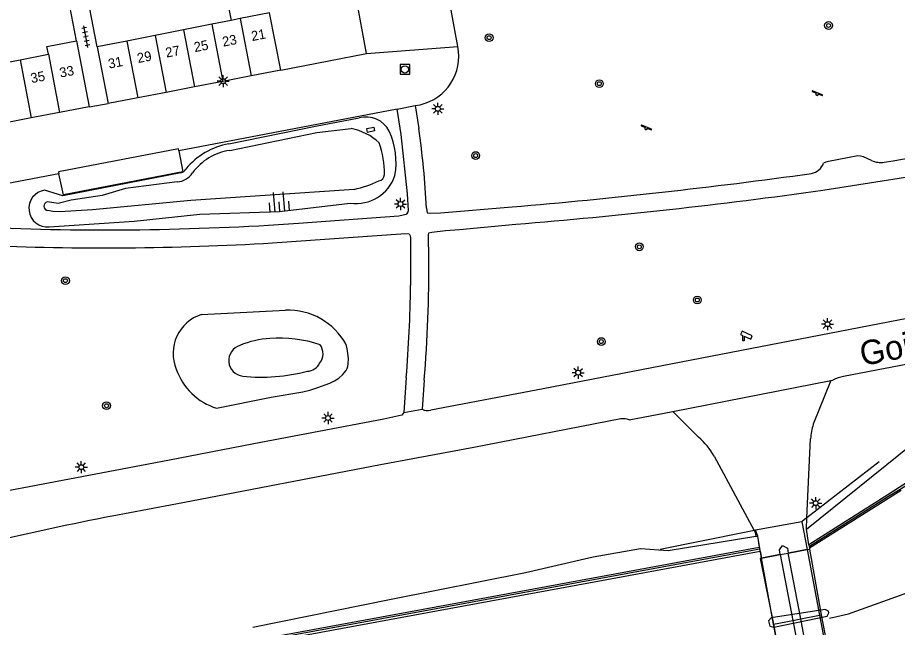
# Model space of a CAD drawing. Extents: x 132999 to 136000, y 398499 to 400501.
# Drawn here: x 133396.4 to 133486.8, y 398848.7 to 398911.3 of the extents above; entities that cross this region are included whole.
import ezdxf

# ---------------------------------------------------------------- set-up
doc = ezdxf.new("R2010")
doc.units = 0
for name, color, linetype in [('gg-afsc-erfafscheiding', 7, 'Continuous'), ('gg-afsc-hekwerk', 7, 'Continuous'), ('gg-afsc-muur', 7, 'Continuous'), ('gg-anno-huisnummerreeks BGT', 7, 'Continuous'), ('gg-anno-openbare ruimte label', 7, 'Continuous'), ('gg-bbg-bijgebouw', 7, 'Continuous'), ('gg-bbg-gedigitaliseerde bebouwing', 7, 'Continuous'), ('gg-bbg-gedigitaliseerde bijgebouw', 7, 'Continuous'), ('gg-bbg-tussenscheiding', 7, 'Continuous'), ('gg-knt-BGT kruinlijn', 7, 'Continuous'), ('gg-knt-bovenkant onderkant talud', 7, 'Continuous'), ('gg-knt-verharding', 7, 'Continuous'), ('gg-knt-verharding niveau 01', 7, 'Continuous'), ('gg-knt-verharding nz', 7, 'Continuous'), ('gg-kntw-beschoeiing', 7, 'Continuous'), ('gg-kwrk-geleidewerk', 7, 'Continuous'), ('gg-kwrk-kunstwerk niveau 01', 7, 'Continuous'), ('gt-grn-vlakafsluiter', 7, 'Continuous'), ('gt-grn-weggrens', 7, 'Continuous'), ('gt-symb-boom', 7, 'Continuous'), ('gt-symb-camera', 7, 'Continuous'), ('gt-symb-kolk center center', 7, 'Continuous'), ('gt-symb-lichtmast', 7, 'Continuous'), ('gt-symb-rioolschacht', 7, 'Continuous'), ('gt-symb-speelvoorziening', 7, 'Continuous'), ('gt-symb-talud symbool', 7, 'Continuous'), ('gt-symb-tegel verharding', 7, 'Continuous'), ('gx-grn-maaiveld', 7, 'Continuous')]:
    doc.layers.add(name, color=color, linetype=linetype)

# ---------------------------------------------------------------- blocks, each defined once
blk = doc.blocks.new('gt0-KOLKCC')
at = {"layer": 'gt-symb-kolk center center'}
blk.add_lwpolyline([(-0.375, 0.2), (0.375, 0.2), (0.375, -0.2), (-0.375, -0.2)], close=True, dxfattribs=at)
blk = doc.blocks.new('gt0-LMAST')
at = {"layer": 'gt-symb-lichtmast'}
for p, q in [((-0.182, 0.173), (-0.447, 0.438)), ((-0.005, 0.246), (-0.005, 0.621)), ((0.172, 0.173), (0.437, 0.438)), ((-0.255, -0.004), (-0.63, -0.004)), ((-0.182, -0.181), (-0.447, -0.446)), ((-0.005, -0.254), (-0.005, -0.629)), ((0.437, -0.446), (0.172, -0.181)), ((0.245, -0.004), (0.62, -0.004))]:
    blk.add_line(p, q, dxfattribs=at)
blk.add_circle((-0.005, -0.004), 0.25, dxfattribs=at)
blk = doc.blocks.new('gt0-RS')
at = {"layer": 'gt-symb-rioolschacht'}
blk.add_lwpolyline([(-0.5, -0.5), (0.5, -0.5), (0.5, 0.5), (-0.5, 0.5)], close=True, dxfattribs=at)
blk.add_circle((0, 0), 0.375, dxfattribs=at)
blk = doc.blocks.new('gt0-BOOM')
at = {"layer": 'gt-symb-boom'}
for radius in [0.4, 0.2]:
    blk.add_circle((0, 0), radius, dxfattribs=at)
blk = doc.blocks.new('gt0-SV')
at = {"layer": 'gt-symb-speelvoorziening'}
for p, q in [((-0.477, 0.255), (-0.08, 0.096)), ((0.542, -0.076), (-0.449, 0.324)), ((0.125, 0.014), (0.515, -0.143))]:
    blk.add_line(p, q, dxfattribs=at)
for centre, radius, start, end in [((-0.466, 0.291), 0.0369, 63.6251, 252.66016), ((-0.002, -0.005), 0.128, 127.68665, 8.59861), ((0.531, -0.111), 0.0363, 243.50852, 72.54358)]:
    blk.add_arc(centre, radius, start, end, dxfattribs=at)
blk = doc.blocks.new('gt0-CAMERA')
at = {"layer": 'gt-symb-camera'}
for points in [[(0.067, 0.484), (0.753, 0.164), (0.916, 0.514), (-0.121, 0.999), (-0.284, 0.648), (-0.067, 0.547)], [(0.067, 0.484), (0.067, 0), (-0.067, 0), (-0.067, 0.547)]]:
    blk.add_lwpolyline(points, dxfattribs=at)
blk = doc.blocks.new('gt0-TEG1')
at = {"layer": 'gt-symb-tegel verharding'}
for p, q in [((-1.125, 0), (1.125, 0)), ((-0.9, -0.25), (-0.9, 0.25)), ((-0.45, -0.25), (-0.45, 0.25)), ((0, -0.25), (0, 0.25)), ((0.45, -0.25), (0.45, 0.25)), ((0.9, -0.25), (0.9, 0.25))]:
    blk.add_line(p, q, dxfattribs=at)
blk = doc.blocks.new('gt0-TALUD_1')
at = {"layer": 'gt-symb-talud symbool'}
for p, q in [((-1, -1), (-1, 0)), ((-0.5, -2), (-0.5, 0)), ((0, -1), (0, 0)), ((0.5, -2), (0.5, 0)), ((1, -1), (1, 0))]:
    blk.add_line(p, q, dxfattribs=at)

msp = doc.modelspace()

# ---------------------------------------------------------------- linework, layer by layer
at = {"layer": 'gg-afsc-erfafscheiding'}
for p, q in [((133402.409, 398908.948), (133401.17, 398915.344)), ((133404.553, 398908.312), (133403.743, 398912.387))]:
    msp.add_line(p, q, dxfattribs=at)
at = {"layer": 'gg-afsc-hekwerk'}
for p, q in [((133484.899, 398865.678), (133477.456, 398859.912)), ((133477.229, 398859.736), (133476.948, 398859.518)), ((133477.456, 398859.912), (133477.229, 398859.736)), ((133476.948, 398859.518), (133477.487, 398856.671)), ((133471.036, 398858.431), (133462.374, 398856.682)), ((133472.045, 398858.635), (133471.036, 398858.431)), ((133472.195, 398858.665), (133472.045, 398858.635)), ((133472.419, 398858.037), (133472.195, 398858.665)), ((133474.729, 398856.146), (133476.018, 398849.386)), ((133476.823, 398849.542), (133475.544, 398856.301)), ((133477.487, 398856.671), (133478.767, 398849.918)), ((133476.018, 398849.386), (133477.829, 398839.889)), ((133478.62, 398840.037), (133476.823, 398849.542))]:
    msp.add_line(p, q, dxfattribs=at)
for points in [[(133474.043, 398849.004), (133472.788, 398855.776), (133472.419, 398858.037)], [(133474.729, 398856.146), (133474.634, 398856.643), (133474.97, 398857.079), (133475.45, 398856.801), (133475.544, 398856.302)], [(133478.767, 398849.918), (133480.439, 398841.096), (133480.639, 398840.861)], [(133475.665, 398840.028), (133475.725, 398840.213), (133474.043, 398849.004)]]:
    msp.add_lwpolyline(points, dxfattribs=at)
at = {"layer": 'gg-afsc-muur'}
for points in [[(133477.721, 398857.001), (133485.853, 398862.136), (133487.043, 398862.884), (133491.665, 398865.805), (133491.806, 398865.833)], [(133472.587, 398856.696), (133472.231, 398856.63), (133456.851, 398853.792), (133440.667, 398850.81), (133421.336, 398847.253), (133415.37, 398846.154), (133409.432, 398845.103), (133403.529, 398844.097), (133397.579, 398843.125), (133391.652, 398842.19), (133385.708, 398841.335), (133379.726, 398840.569), (133373.787, 398839.803), (133367.81, 398839.049), (133361.852, 398838.439), (133355.825, 398837.84), (133349.854, 398837.251), (133343.856, 398836.777), (133337.878, 398836.337)]]:
    msp.add_lwpolyline(points, dxfattribs=at)
at = {"layer": 'gg-bbg-bijgebouw'}
for p, q in [((133423.41, 398905.91), (133422.26, 398911.81)), ((133423.41, 398905.91), (133420.377, 398905.325)), ((133420.377, 398905.325), (133417.461, 398904.762)), ((133414.545, 398904.2), (133411.628, 398903.637)), ((133417.461, 398904.762), (133414.545, 398904.2)), ((133408.712, 398903.075), (133405.68, 398902.49)), ((133411.628, 398903.637), (133408.712, 398903.075)), ((133400.683, 398901.569), (133397.766, 398901.009)), ((133403.71, 398902.15), (133400.683, 398901.569)), ((133397.766, 398901.009), (133394.85, 398900.45))]:
    msp.add_line(p, q, dxfattribs=at)
at = {"layer": 'gg-bbg-gedigitaliseerde bebouwing'}
msp.add_line((133416.899, 398918.366), (133418.291, 398911.026), dxfattribs=at)
at = {"layer": 'gg-bbg-gedigitaliseerde bijgebouw'}
for p, q in [((133416.328, 398910.638), (133413.414, 398910.063)), ((133418.291, 398911.026), (133416.328, 398910.638)), ((133410.499, 398909.487), (133407.586, 398908.911)), ((133413.414, 398910.063), (133410.499, 398909.487)), ((133402.409, 398908.948), (133403.71, 398902.15)), ((133407.586, 398908.911), (133404.553, 398908.312)), ((133404.553, 398908.312), (133405.68, 398902.49)), ((133393.705, 398906.42), (133396.618, 398906.991)), ((133396.618, 398906.991), (133399.533, 398907.563))]:
    msp.add_line(p, q, dxfattribs=at)
msp.add_lwpolyline([(133399.533, 398907.563), (133399.379, 398908.367), (133402.409, 398908.948)], dxfattribs=at)
at = {"layer": 'gg-bbg-tussenscheiding'}
for p, q in [((133419.241, 398911.214), (133418.291, 398911.026)), ((133422.26, 398911.81), (133419.241, 398911.214)), ((133419.241, 398911.214), (133420.377, 398905.325)), ((133416.328, 398910.638), (133417.461, 398904.762)), ((133410.499, 398909.487), (133411.628, 398903.637)), ((133413.414, 398910.063), (133414.545, 398904.2)), ((133407.586, 398908.911), (133408.712, 398903.075)), ((133396.618, 398906.991), (133397.766, 398901.009)), ((133399.533, 398907.563), (133400.683, 398901.569))]:
    msp.add_line(p, q, dxfattribs=at)
at = {"layer": 'gg-knt-BGT kruinlijn'}
for p, q in [((133472.206, 398858.002), (133463.217, 398856.544)), ((133460.371, 398856.754), (133455.513, 398855.898)), ((133463.217, 398856.544), (133460.371, 398856.754)), ((133455.513, 398855.898), (133448.565, 398854.282)), ((133448.565, 398854.282), (133434.733, 398851.533)), ((133434.733, 398851.533), (133420.546, 398848.638))]:
    msp.add_line(p, q, dxfattribs=at)
at = {"layer": 'gg-knt-bovenkant onderkant talud'}
msp.add_line((133415.249, 398880.806), (133423.888, 398881.259), dxfattribs=at)
for points in [[(133418.064, 398898.363), (133426.973, 398900.172), (133431.45, 398901.011)], [(133418.158, 398897.674), (133427.106, 398899.531), (133430.642, 398899.916)], [(133413.151, 398895.372), (133401.018, 398893.003), (133399.139, 398893.588)], [(133412.758, 398894.431), (133407.436, 398893.772), (133405.065, 398893.031), (133401.864, 398892.561), (133400.525, 398892.21), (133399.424, 398892.375)], [(133430.941, 398893.673), (133414.154, 398892.519), (133404.068, 398891.58), (133400.702, 398891.379), (133399.977, 398891.409), (133399.474, 398891.502)], [(133399.6, 398889.82), (133408.349, 398890.415), (133415.08, 398891.134), (133423.282, 398891.383), (133430.549, 398892.252)], [(133416.814, 398871.184), (133422.412, 398872.309), (133425.66, 398872.864), (133426.373, 398873.039), (133427.123, 398873.277), (133428.44, 398873.757), (133428.915, 398873.983), (133429.353, 398874.259), (133429.752, 398874.606), (133430.107, 398875.045), (133430.216, 398875.251), (133430.291, 398875.486), (133430.336, 398875.742), (133430.353, 398876.285), (133430.305, 398876.818), (133430.226, 398877.276), (133430.12, 398877.718)]]:
    msp.add_lwpolyline(points, dxfattribs=at)
for centre, radius, start, end in [((133432.169, 398898.437), 2.673, 26.94331, 105.6159), ((133429.649, 398894.473), 5.533, 45.8072, 79.66298), ((133427.511, 398896.431), 7.741, 350.01833, 24.55641), ((133419.499, 398890.85), 7.649, 100.80943, 140.0232), ((133418.981, 398892.019), 5.715, 98.28094, 144.18451), ((133425.131, 398895.369), 8.92, 359.01731, 20.13781), ((133412.571, 398896.57), 2.147, 274.98663, 325.79938), ((133413.021, 398896.031), 0.671, 281.1827, 336.59551), ((133431.13, 398896.437), 4.226, 262.09252, 341.39117), ((133433.36, 398895.213), 0.69, 279.95394, 0.25363), ((133428.154, 398906.074), 12.71, 282.66757, 294.77028), ((133399.426, 398891.711), 1.899, 98.67952, 275.27098), ((133399.513, 398891.942), 0.442, 101.65355, 264.90238), ((133416.518, 398876.83), 4.174, 107.69974, 202.79026), ((133424.157, 398874.477), 6.787, 28.52223, 92.2676), ((133422.849, 398868.832), 9.531, 93.34765, 112.44877), ((133423.321, 398865.657), 12.732, 71.13832, 94.63632), ((133419.681, 398876.09), 1.621, 106.92604, 263.80244), ((133426.192, 398876.778), 1.552, 321.09908, 36.67203), ((133418.676, 398877.244), 6.34, 198.68842, 252.92386), ((133426.105, 398876.424), 1.436, 271.23467, 334.39143), ((133421.423, 398892.908), 18.53, 264.06204, 284.73537)]:
    msp.add_arc(centre, radius, start, end, dxfattribs=at)
at = {"layer": 'gg-knt-verharding'}
for p, q in [((133432.217, 398907.621), (133430.564, 398916.706)), ((133441.582, 398908.354), (133440.6, 398913.726)), ((133435.372, 398901.912), (133437.212, 398902.273)), ((133437.212, 398902.273), (133437.735, 398902.374)), ((133437.212, 398902.273), (133437.575, 398899.936)), ((133435.372, 398901.912), (133412.935, 398897.637)), ((133400.611, 398895.27), (133382.612, 398891.837)), ((133436.294, 398874.326), (133436.049, 398870.729)), ((133438.128, 398874.062), (133437.916, 398871.079)), ((133463.674, 398870.848), (133479.906, 398874.034)), ((133479.906, 398874.034), (133478.119, 398869.537)), ((133479.906, 398874.034), (133480.127, 398874.079)), ((133459.183, 398869.984), (133463.674, 398870.848)), ((133463.674, 398870.848), (133466.338, 398868.198)), ((133477.456, 398859.912), (133477.832, 398868.049)), ((133467.926, 398866.254), (133472.045, 398858.635)), ((133477.402, 398858.742), (133477.456, 398859.912)), ((133472.045, 398858.635), (133472.151, 398858.438)), ((133472.151, 398858.438), (133472.206, 398858.002)), ((133477.643, 398857.158), (133477.402, 398858.742))]:
    msp.add_line(p, q, dxfattribs=at)
for points in [[(133423.41, 398905.91), (133428.347, 398906.881), (133432.217, 398907.621)], [(133436.524, 398891.501), (133436.432, 398893.2), (133435.774, 398899.324), (133435.372, 398901.912)], [(133479.084, 398893.577), (133493.026, 398895.784), (133500.764, 398897.149), (133507.378, 398898.348), (133525.595, 398902.017)], [(133624.793, 398901.816), (133597.525, 398896.712), (133569.223, 398891.245), (133539.04, 398885.465), (133508.892, 398879.76), (133481.237, 398874.445)], [(133412.935, 398897.637), (133413.349, 398895.473), (133401.074, 398893.123), (133400.611, 398895.27)], [(133484.109, 398896.643), (133483.272, 398897.031), (133482.984, 398897.099), (133482.691, 398897.115), (133479.682, 398896.549), (133479.422, 398896.476), (133479.177, 398896.359)], [(133438.369, 398891.748), (133438.434, 398891.26), (133438.808, 398891.24), (133439.813, 398891.262), (133447.178, 398891.88)], [(133425.209, 398890.194), (133435.525, 398890.944), (133436.298, 398891.111)], [(133438.603, 398886.705), (133438.586, 398888.807), (133438.573, 398889.007), (133438.626, 398889.206), (133438.913, 398889.282), (133440.317, 398889.442), (133441.753, 398889.555), (133447.559, 398890.088)], [(133422.561, 398888.172), (133435.725, 398889.11), (133436.165, 398889.132), (133436.602, 398889.108), (133436.693, 398888.91), (133436.735, 398888.695), (133436.745, 398883.78)], [(133491.018, 398881), (133490.937, 398881.023), (133450.352, 398873.181), (133438.821, 398870.969)], [(133436.049, 398870.729), (133435.858, 398870.466), (133434.005, 398870.058), (133420.622, 398867.535), (133411.811, 398865.815), (133391.567, 398861.986), (133386.081, 398860.842)], [(133458.358, 398870.087), (133443.241, 398867.157), (133433.662, 398865.369), (133413.351, 398861.476), (133406.085, 398860.101)]]:
    msp.add_lwpolyline(points, dxfattribs=at)
for centre, radius, start, end in [((133436.613, 398907.323), 5.074, 282.76911, 11.72364), ((133357.287, 398888.018), 81.167, 2.63398, 8.44347), ((133424.978, 399300.208), 408.227, 278.50904, 280.63906), ((133477.627, 398896.929), 1.651, 280.25074, 339.80764), ((133484.988, 398898.384), 1.95, 243.21398, 281.6616), ((133400.169, 399453.691), 563.774, 274.78308, 277.92717), ((133402.141, 399444.63), 556.399, 274.68216, 277.94875), ((133435.928, 398891.586), 0.602, 307.92436, 351.89216), ((133405.353, 399176.701), 287.194, 267.45984, 273.9644), ((133405.189, 399180.033), 292.378, 267.5213, 273.40635), ((133311.54, 398885.148), 127.073, 354.99491, 0.70189), ((133302.915, 398885.427), 133.84, 355.24248, 359.29511), ((133481.817, 398870.819), 3.672, 99.09207, 117.40578), ((133438.516, 398872.234), 1.302, 242.56992, 283.56981), ((133458.612, 398868.765), 1.346, 64.89404, 100.87302), ((133483.71, 398867.687), 5.889, 161.69068, 176.47543), ((133462.217, 398863.211), 6.469, 28.05738, 50.43149), ((133471.727, 398522.571), 343.854, 101.00539, 103.11783)]:
    msp.add_arc(centre, radius, start, end, dxfattribs=at)
at = {"layer": 'gg-knt-verharding niveau 01'}
for p, q in [((133477.727, 398856.717), (133478.93, 398849.95)), ((133476.823, 398849.542), (133478.767, 398849.918)), ((133478.767, 398849.918), (133478.93, 398849.95)), ((133478.93, 398849.95), (133480.639, 398840.861)), ((133474.043, 398849.004), (133476.018, 398849.386)), ((133474.043, 398849.004), (133475.665, 398840.028)), ((133476.018, 398849.386), (133476.823, 398849.542))]:
    msp.add_line(p, q, dxfattribs=at)
msp.add_lwpolyline([(133472.788, 398855.776), (133472.644, 398855.749), (133474.043, 398849.004)], dxfattribs=at)
at = {"layer": 'gg-knt-verharding nz'}
msp.add_line((133436.049, 398870.729), (133437.916, 398871.079), dxfattribs=at)
msp.add_lwpolyline([(133412.935, 398897.637), (133412.898, 398897.832), (133400.565, 398895.486), (133400.611, 398895.27)], dxfattribs=at)
at = {"layer": 'gg-kntw-beschoeiing'}
msp.add_line((133477.487, 398856.671), (133477.727, 398856.717), dxfattribs=at)
msp.add_line((133477.487, 398856.671), (133477.727, 398856.717), dxfattribs=at)
at = {"layer": 'gg-kwrk-geleidewerk'}
msp.add_lwpolyline([(133479.795, 398849.63), (133481.744, 398850.057), (133494.996, 398854.826)], dxfattribs=at)
at = {"layer": 'gg-kwrk-kunstwerk niveau 01'}
for p, q in [((133474.729, 398856.146), (133472.788, 398855.776)), ((133474.729, 398856.146), (133475.544, 398856.301)), ((133477.487, 398856.671), (133475.544, 398856.301))]:
    msp.add_line(p, q, dxfattribs=at)
at = {"layer": 'gt-grn-vlakafsluiter'}
for p, q in [((133403.71, 398902.15), (133405.68, 398902.49)), ((133472.206, 398858.002), (133472.419, 398858.037))]:
    msp.add_line(p, q, dxfattribs=at)
at = {"layer": 'gt-grn-weggrens'}
for p, q in [((133432.217, 398907.621), (133441.582, 398908.354)), ((133476.948, 398859.518), (133472.195, 398858.665))]:
    msp.add_line(p, q, dxfattribs=at)
at = {"layer": 'gx-grn-maaiveld'}
for p, q in [((133472.604, 398856.903), (133472.419, 398858.037)), ((133477.643, 398857.158), (133477.713, 398856.789)), ((133472.669, 398856.508), (133472.604, 398856.903)), ((133474.729, 398856.146), (133475.544, 398856.302)), ((133475.544, 398856.302), (133477.487, 398856.671)), ((133477.713, 398856.789), (133477.727, 398856.717))]:
    msp.add_line(p, q, dxfattribs=at)
for points in [[(133477.402, 398858.742), (133488.32, 398867.54), (133553.46, 398879.08), (133576.63, 398879.75), (133589.479, 398882.154)], [(133585.481, 398878.925), (133584.654, 398878.891), (133571.83, 398878.437), (133559.434, 398878.015), (133559.124, 398877.991), (133559.117, 398878.029), (133538.821, 398874.411), (133515.589, 398870.269), (133491.771, 398866.03), (133491.775, 398866.005), (133491.599, 398865.97), (133486.949, 398863.032), (133485.759, 398862.284), (133477.643, 398857.158)], [(133487.136, 398862.736), (133485.946, 398861.988), (133477.713, 398856.789)], [(133337.863, 398836.536), (133343.841, 398836.976), (133349.836, 398837.45), (133355.805, 398838.039), (133361.832, 398838.638), (133367.787, 398839.248), (133373.762, 398840.001), (133379.701, 398840.767), (133385.681, 398841.533), (133391.622, 398842.388), (133397.547, 398843.322), (133403.496, 398844.294), (133409.398, 398845.3), (133415.334, 398846.351), (133421.3, 398847.45), (133440.631, 398851.007), (133456.815, 398853.989), (133472.195, 398856.827), (133472.604, 398856.903)], [(133337.892, 398836.137), (133343.871, 398836.577), (133349.871, 398837.052), (133355.844, 398837.641), (133361.872, 398838.24), (133367.832, 398838.851), (133373.813, 398839.604), (133379.752, 398840.37), (133385.735, 398841.137), (133391.682, 398841.993), (133397.61, 398842.927), (133403.562, 398843.9), (133409.467, 398844.906), (133415.405, 398845.957), (133421.373, 398847.057), (133440.703, 398850.614), (133456.888, 398853.596), (133472.268, 398856.434), (133472.669, 398856.508)], [(133472.669, 398856.508), (133472.788, 398855.777), (133474.729, 398856.146)], [(133479.664, 398850.33), (133479.331, 398850.503), (133473.801, 398849.658), (133473.498, 398849.326), (133473.66, 398848.786), (133474.06, 398848.69), (133479.549, 398849.812), (133479.727, 398850.168), (133479.664, 398850.33)]]:
    msp.add_lwpolyline(points, dxfattribs=at)

# ---------------------------------------------------------------- block references
at = {"layer": 'gt-symb-boom'}
for p, rotation in [((133479.685, 398910.512), 100.71464389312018), ((133444.81, 398909.255), 100.71464389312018), ((133456.138, 398904.529), 100.71464389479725), ((133443.432, 398897.144), -169.3979417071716)]:
    msp.add_blockref('gt0-BOOM', p, dxfattribs=dict(at, rotation=rotation))
for p in [(133460.24, 398887.77), (133401.282, 398884.296), (133466.202, 398882.301), (133456.334, 398878.033), (133405.503, 398871.44)]:
    msp.add_blockref('gt0-BOOM', p, dxfattribs=at)
at = {"layer": 'gt-symb-camera'}
msp.add_blockref('gt0-CAMERA', (133470.936, 398878.106), dxfattribs=at)
at = {"layer": 'gt-symb-kolk center center', "rotation": 10.985497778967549}
msp.add_blockref('gt0-KOLKCC', (133432.636, 398899.798), dxfattribs=at)
at = {"layer": 'gt-symb-lichtmast'}
for p in [(133417.492, 398904.8), (133439.553, 398901.951), (133435.709, 398892.171), (133479.581, 398879.821), (133453.965, 398874.841), (133428.263, 398870.184), (133402.915, 398865.126), (133478.37, 398861.434)]:
    msp.add_blockref('gt0-LMAST', p, dxfattribs=at)
at = {"layer": 'gt-symb-rioolschacht'}
msp.add_blockref('gt0-RS', (133436.154, 398905.997), dxfattribs=at)
at = {"layer": 'gt-symb-speelvoorziening'}
for p in [(133478.5, 398903.46), (133460.938, 398899.94)]:
    msp.add_blockref('gt0-SV', p, dxfattribs=at)
at = {"layer": 'gt-symb-talud symbool', "xscale": 0.9998169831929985, "yscale": 0.9998169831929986, "rotation": -175.69798887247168}
msp.add_blockref('gt0-TALUD_1', (133423.282, 398891.383), dxfattribs=at)
at = {"layer": 'gt-symb-tegel verharding', "rotation": 100.83791044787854}
msp.add_blockref('gt0-TEG1', (133403.379, 398909.359), dxfattribs=at)

# ---------------------------------------------------------------- texts
at = {"layer": 'gg-anno-huisnummerreeks BGT'}
for s, p in [('23', (133417.493, 398908.333)), ('21', (133420.468, 398908.907)), ('25', (133414.578, 398907.771)), ('29', (133408.745, 398906.646)), ('27', (133411.66, 398907.208)), ('31', (133405.77, 398906.072)), ('35', (133397.801, 398904.579)), ('33', (133400.774, 398905.15))]:
    msp.add_text(s, height=1, rotation=10.9, dxfattribs=at).set_placement(p)
at = {"layer": 'gg-anno-openbare ruimte label'}
msp.add_text('Goirkekanaaldijk', height=2.5, rotation=11.2, dxfattribs=at).set_placement((133483.159, 398875.505))

doc.saveas('drawing.dxf')
